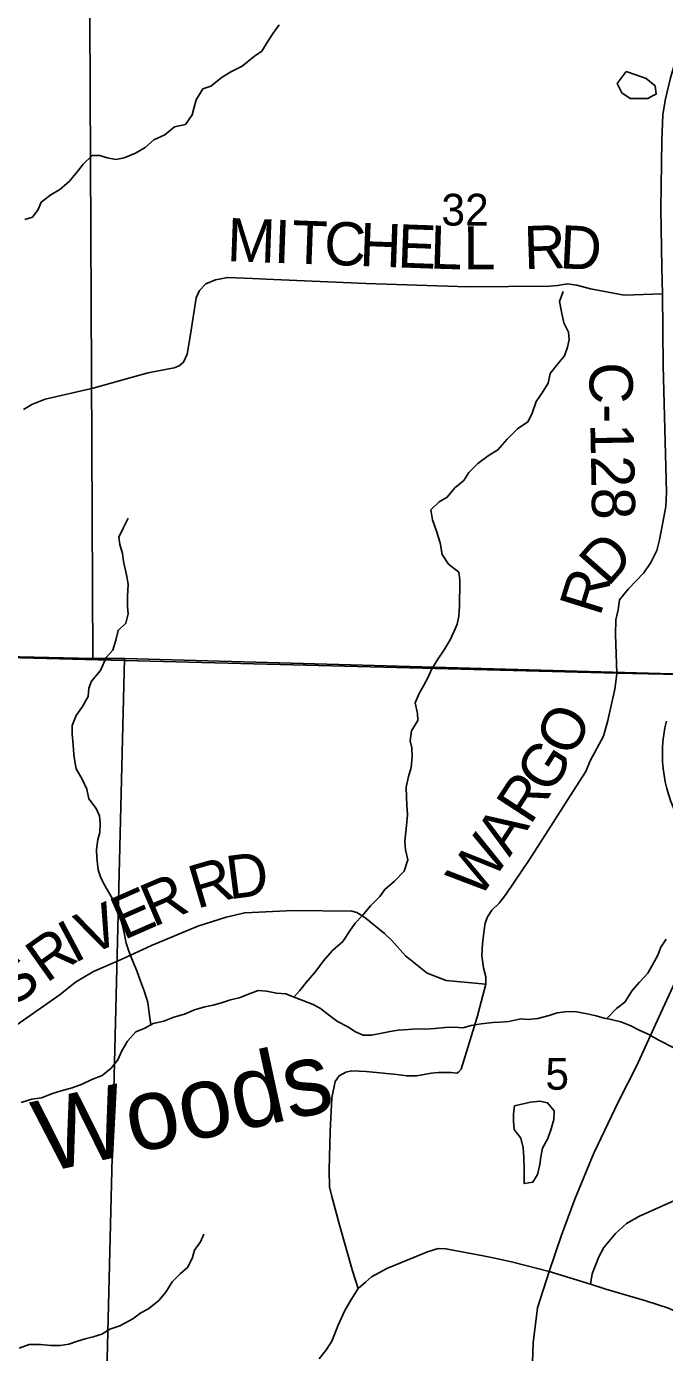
# Model space of a CAD drawing. Extents: x 2043100 to 2470832, y 443715 to 810583.
# Drawn here: x 2231654 to 2236081, y 666237 to 675442 of the extents above; entities that cross this region are included whole.
import ezdxf

# ---------------------------------------------------------------- set-up
doc = ezdxf.new("R2010")
doc.units = 0
for name, color, linetype in [('GM_X_County_Road', 7, 'Continuous'), ('GM_X_County_Road_Text', 7, 'Continuous'), ('GM_X_Interstate_Route', 7, 'Continuous'), ('GM_X_Interstate_Shield', 7, 'Continuous'), ('GM_X_Minor_Lake', 7, 'Continuous'), ('GM_X_Minor_River', 7, 'Continuous'), ('GM_X_Minor_River_Text', 7, 'Continuous'), ('GM_X_Section', 7, 'Continuous'), ('GM_X_Section_Text', 7, 'Continuous'), ('GM_X_Township', 7, 'Continuous'), ('GM_X_Township_Road', 7, 'Continuous'), ('GM_X_Township_Road_Text', 7, 'Continuous')]:
    doc.layers.add(name, color=color, linetype=linetype)

msp = doc.modelspace()

# ---------------------------------------------------------------- linework, layer by layer
at = {"layer": 'GM_X_County_Road'}
for points in [[(2235748.3, 670928.3), (2235751.5, 670952.9), (2235742.4, 671220.3), (2235743.7, 671322.2), (2235761, 671391.1), (2235768.7, 671460.5), (2235830.1, 671535), (2235937.3, 671650.1), (2235986.8, 671720.5), (2236028.1, 671805), (2236047.6, 671879.2), (2236076.5, 672035.7), (2236090, 672109.9), (2236095.3, 672208.1), (2236073.1, 673087.1), (2236067.6, 673585.7), (2236062.3, 673767.9), (2236057.4, 674176.4), (2236064.1, 674647.1), (2236070.8, 674831.3), (2236088, 674939.6), (2236123, 675086.1), (2236214.8, 675397.2), (2236277.2, 675620)], [(2234788.4, 668589.8), (2234788.9, 668591.7), (2234842, 668793.3), (2234841.6, 668843.4), (2234825.2, 668907.3), (2234814.6, 668993.4), (2234818, 669073.5), (2234831.3, 669169.8), (2234837, 669217.9), (2234852.7, 669262.1), (2234884.3, 669308.4), (2234933.9, 669356.9), (2234979.5, 669415.3), (2235143.7, 669659), (2235309.8, 669916.7), (2235426.4, 670101.8), (2235535.2, 670270.9), (2235566.7, 670343.3), (2235659, 670515.6), (2235689.4, 670624.2), (2235737.1, 670841.5), (2235748.3, 670928.3)], [(2231470.1, 668430.1), (2231887.9, 668721.8), (2231993.2, 668806.7), (2232118.6, 668881.9), (2232312, 668965.5), (2232521.2, 669061.3), (2232842.1, 669196), (2233039.5, 669257.7), (2233169.3, 669288.8), (2233507, 669305.5), (2233910.8, 669300.7), (2233946.9, 669290.9), (2234003.1, 669255.3), (2234137.8, 669146.2), (2234190.1, 669096.6), (2234284.8, 668989.2), (2234435.6, 668870.2), (2234565.9, 668819.1), (2234842, 668793.3)], [(2233955.8, 666681), (2233916.5, 666802.9), (2233828.4, 667114.7), (2233772.9, 667318.6), (2233756.5, 667386.5), (2233753.6, 667504.7), (2233761.7, 667773.2), (2233774.1, 668003.6), (2233797.3, 668118), (2233823, 668158.3), (2233870.8, 668182.7), (2233910.7, 668191), (2234010.7, 668187.8), (2234224.7, 668165.5), (2234292.7, 668158), (2234362.7, 668156.5), (2234462.5, 668175.4), (2234512.5, 668179.8), (2234600.4, 668180.5), (2234640.4, 668176.8), (2234652.4, 668182.9), (2234670.2, 668203.1), (2234779.7, 668556.5), (2234788.4, 668589.8)], [(2235567.1, 666711.6), (2235579.1, 666782.6), (2235625.1, 666901.6), (2235659.9, 666966.3), (2235742.3, 667062), (2235819, 667131.5), (2235908.1, 667183.2), (2236372.4, 667392), (2236554.8, 667485.4), (2236679.5, 667559.8), (2236912.6, 667722.3), (2237104.2, 667858.1), (2237185.2, 667915.6), (2237420.4, 668074.1), (2237513.4, 668129.8), (2237628.5, 668184), (2237767.8, 668224.3), (2237779.4, 668227.6)], [(2233686.3, 666191.8), (2233736.2, 666258), (2233774.1, 666314.2), (2233818, 666426.4), (2233859.9, 666524.6), (2233905.8, 666600.8), (2233955.8, 666681), (2234007.7, 666725.1), (2234047.6, 666761.2), (2234155.6, 666819.5), (2234437.4, 666936.1), (2234511.3, 666958.3), (2234565.3, 666956.3), (2234823.2, 666908.7), (2234880.8, 666896), (2234881.2, 666895.9)], [(2234881.2, 666895.9), (2234967.2, 666876.9), (2235029.2, 666862.9), (2235282.4, 666798.9), (2235567.1, 666711.6), (2235675.1, 666675.7), (2235951.1, 666596), (2236109.1, 666544.2), (2236175.1, 666514.2), (2236246.3, 666465.7), (2236246.7, 666465.5)]]:
    msp.add_lwpolyline(points, dxfattribs=at)
at = {"layer": 'GM_X_Interstate_Route'}
msp.add_lwpolyline([(2235161.2, 666032.3), (2235170.2, 666303), (2235201.3, 666545.9), (2235282.4, 666798.9), (2235365.8, 667051.9), (2235459.2, 667301.3), (2235591.9, 667619.2), (2235762.2, 667979.6), (2235887.7, 668223.4), (2236055.9, 668593.7), (2236241.8, 668994.3), (2236404.6, 669310.5), (2236537.9, 669576.3), (2236662.8, 669876.1), (2236767.3, 670193.5), (2236871.9, 670530.8), (2236935, 670928.2), (2236962.4, 671258.1), (2236970.9, 671749.7), (2236947, 672108.3), (2236889.3, 672310), (2236776, 673758.8), (2236599.3, 675527.4)], dxfattribs=at)
at = {"layer": 'GM_X_Interstate_Shield'}
msp.add_arc((2237004.3, 670389.5), 937.5, 165.80665, 258.46304, dxfattribs=at)
at = {"layer": 'GM_X_Minor_Lake'}
for points in [[(2235816.7, 675130.5), (2235753, 675046.2), (2235785.2, 674980.3), (2235843.3, 674942.5), (2235965.2, 674942.9), (2236008.5, 674965.5)], [(2236008.5, 674965.5), (2236023.1, 674973.1), (2236017, 675029.1), (2235954.8, 675081), (2235882.8, 675106.7), (2235816.7, 675130.5)], [(2235040.6, 667949.6), (2235034.7, 667893.5), (2235034.9, 667843.4), (2235039.1, 667785.4), (2235085.2, 667723.5), (2235101.4, 667657.5), (2235105.6, 667589.4), (2235107.9, 667509.3), (2235108.2, 667409.2), (2235168.1, 667419.5), (2235193.2, 667460.6)], [(2235193.2, 667460.6), (2235199.9, 667471.6), (2235215.7, 667541.8), (2235223.6, 667593.8), (2235235.4, 667654), (2235271.1, 667722.2), (2235294.9, 667790.3), (2235314.7, 667854.4), (2235316.6, 667914.5), (2235270.4, 667970.4), (2235216.4, 667982.2), (2235152.4, 667974), (2235040.6, 667949.6)]]:
    msp.add_lwpolyline(points, dxfattribs=at)
at = {"layer": 'GM_X_Minor_River'}
for points in [[(2231641.6, 674102.9), (2231695.5, 674119.1), (2231735.4, 674171.3), (2231755.2, 674221.4), (2231823, 674273.7), (2231884.9, 674309.9), (2231950.7, 674366.2), (2232008.5, 674434.4), (2232046.3, 674486.6), (2232110.1, 674546.9), (2232162.1, 674545.1), (2232214.1, 674529.2), (2232274.1, 674519.4), (2232332, 674529.7), (2232409.9, 674562), (2232477.8, 674602.2), (2232537.6, 674654.5), (2232613.5, 674688.8), (2232681.3, 674745.1), (2232757.2, 674761.4), (2232803, 674827.6), (2232818.8, 674881.7), (2232832.6, 674931.8), (2232878.4, 675008), (2232934.3, 675028.2), (2233012.1, 675090.5), (2233072, 675126.8), (2233151.8, 675167.1), (2233235.6, 675235.4), (2233287.4, 675271.7), (2233331.2, 675341.9), (2233365, 675396), (2233406.8, 675452.2)], [(2233509.5, 668703.1), (2233550.8, 668749.1), (2233604.6, 668817.3), (2233654.4, 668875.5), (2233714.1, 668955.8), (2233777.9, 669028.1), (2233849.6, 669090.4), (2233897.4, 669164.7), (2233935.2, 669216.9), (2233985, 669271.1), (2234040.8, 669337.4), (2234106.6, 669401.7), (2234140.4, 669451.8), (2234208.2, 669508.1), (2234274, 669578.4), (2234299.7, 669656.6), (2234283.5, 669726.6), (2234279.4, 669786.6), (2234291, 669894.8), (2234298.8, 669968.9), (2234292.6, 670036.9), (2234290.4, 670090.9), (2234288.2, 670161), (2234306, 670235.1), (2234323.8, 670297.2), (2234331.6, 670371.3), (2234329.4, 670433.4), (2234317.2, 670483.4), (2234325, 670551.5), (2234368.8, 670623.7), (2234368.7, 670673.7), (2234352.4, 670745.8), (2234378.2, 670811.9), (2234408.1, 670864), (2234441.9, 670924.2), (2234465.7, 670978.3), (2234509.5, 671048.6), (2234553.2, 671114.8), (2234595, 671185), (2234622.8, 671243.1), (2234642.7, 671293.2), (2234654.5, 671349.3), (2234658.3, 671417.4), (2234660.1, 671471.5), (2234662, 671533.5), (2234661.8, 671601.6), (2234653.6, 671653.6), (2234583.5, 671709.4), (2234539.3, 671777.3), (2234525, 671857.3), (2234498.8, 671939.3), (2234472.6, 672017.3), (2234460.4, 672085.3), (2234518.2, 672141.5), (2234574.1, 672173.8), (2234625.9, 672238), (2234689.7, 672290.3), (2234723.5, 672346.4), (2234787.3, 672408.7), (2234857.1, 672461), (2234924.9, 672503.3), (2234988.7, 672577.6), (2235062.5, 672647.9), (2235132.3, 672696.2), (2235160.1, 672750.3), (2235191.8, 672838.5), (2235233.6, 672898.7), (2235273.4, 672966.9), (2235287.2, 673033), (2235341, 673099.2), (2235388.8, 673155.4), (2235408.6, 673215.6), (2235420.4, 673269.7), (2235416.3, 673319.7), (2235384.1, 673385.6), (2235365.9, 673461.6), (2235353.7, 673533.6), (2235379.5, 673601.8)], [(2232518.1, 668512.4), (2232505.7, 668593.2), (2232495.5, 668667.2), (2232473.3, 668741.2), (2232445.1, 668815.2), (2232420.9, 668887.2), (2232388.7, 668957.2), (2232364.5, 669023.1), (2232346.3, 669077.1), (2232332.1, 669149.1), (2232317.9, 669209.1), (2232301.8, 669267.1), (2232277.6, 669333.1), (2232241.4, 669403), (2232199.2, 669475), (2232171, 669530.9), (2232150.9, 669586.9), (2232142.6, 669670.9), (2232140.5, 669729), (2232150.2, 669797.1), (2232162.1, 669847.2), (2232165.9, 669911.2), (2232161.7, 669961.3), (2232137.6, 670013.2), (2232087.4, 670079.1), (2232073.2, 670147.1), (2232041, 670217.1), (2231998.8, 670289), (2231988.7, 670339), (2231982.5, 670389), (2231978.3, 670455.1), (2231972.1, 670529.1), (2231969.9, 670589.2), (2231999.7, 670659.3), (2232043.5, 670721.5), (2232081.3, 670791.7), (2232087.1, 670847.8), (2232105, 670897.9), (2232166.7, 670972.2), (2232206.4, 671062.4), (2232252.3, 671112.6), (2232274, 671182.7), (2232289.8, 671248.8), (2232343.7, 671299.1), (2232359.5, 671365.2), (2232355.3, 671415.2), (2232355.1, 671485.3), (2232360.8, 671569.4), (2232348.7, 671635.4), (2232328.4, 671727.4), (2232320.2, 671783.4), (2232302, 671845.4), (2232295.9, 671897.4), (2232327.7, 671963.6), (2232359.5, 672027.8)], [(2235682.1, 668554.5), (2235748.2, 668624.8), (2235806.1, 668669), (2235857.8, 668749.3), (2235907.6, 668807.5), (2235965.4, 668869.8), (2235999.2, 668927.9), (2236035, 668994.1), (2236056.8, 669050.2), (2236092.6, 669106.4)], [(2231618, 667971.5), (2231691.8, 667995.8), (2231757.8, 668004), (2231835.7, 668034.3), (2231895.6, 668052.5), (2231971.5, 668072.8), (2232039.4, 668099.1), (2232107.3, 668131.4), (2232179.1, 668159.6), (2232241, 668209.9), (2232288.8, 668268.1), (2232316.6, 668330.3), (2232354.4, 668398.5), (2232412.1, 668462.8), (2232476, 668489), (2232533.9, 668521.2), (2232607.8, 668537.5), (2232677.7, 668563.8), (2232751.6, 668586.1), (2232819.5, 668616.3), (2232891.4, 668636.6), (2232949.4, 668646.8), (2233007.3, 668665.1), (2233069.2, 668685.3), (2233131.1, 668699.5), (2233207, 668727.8), (2233262.9, 668750), (2233318.9, 668744.2), (2233388.9, 668730.5), (2233452.9, 668726.7), (2233504.9, 668704.9), (2233571, 668679.1), (2233643, 668653.3), (2233695.1, 668625.5), (2233747.2, 668583.6), (2233813.3, 668533.8), (2233883.4, 668498), (2233937.5, 668462.2), (2233991.5, 668440.3), (2234047.5, 668440.5), (2234119.4, 668452.8), (2234177.4, 668465), (2234233.3, 668473.2), (2234305.3, 668479.5), (2234361.2, 668483.7)], [(2234361.2, 668483.7), (2234423.2, 668481.9), (2234487.2, 668486.1), (2234559.1, 668492.4), (2234621.1, 668494.6), (2234683.1, 668490.8), (2234739, 668507), (2234808.9, 668517.3), (2234890.9, 668527.6), (2234942.8, 668529.8), (2235000.8, 668534), (2235084.7, 668552.3), (2235136.7, 668548.5), (2235202.7, 668554.7), (2235280.6, 668577), (2235336.5, 668595.3), (2235390.4, 668601.4), (2235460.4, 668603.7), (2235544.4, 668588), (2235608.4, 668574.2), (2235662.5, 668558.4), (2235712.5, 668548.5), (2235778.5, 668532.8), (2235848.5, 668505), (2235900.6, 668477.1), (2235968.7, 668447.4), (2236042.8, 668405.6), (2236142.9, 668353.9)], [(2231603.1, 666267.7), (2231673, 666291.9), (2231751, 666292.2), (2231823, 666284.4), (2231886.9, 666284.7), (2231948.9, 666294.9), (2232008.8, 666315.1), (2232060.7, 666331.3), (2232116.7, 666345.5), (2232176.6, 666363.8), (2232232.5, 666398), (2232302.4, 666422.3), (2232392.2, 666470.7), (2232448, 666510.9), (2232501.9, 666539.1), (2232571.7, 666597.4), (2232621.5, 666655.7), (2232665.3, 666727.9), (2232721.1, 666782.2), (2232772.9, 666828.4), (2232806.7, 666896.6), (2232820.5, 666946.7), (2232862.4, 667004.9), (2232884.2, 667057)]]:
    msp.add_lwpolyline(points, dxfattribs=at)
at = {"layer": 'GM_X_Section'}
for points in [[(2237342.8, 676305.5), (2237290.7, 670914.8), (2232335.3, 671053.3), (2232115.2, 671055.1), (2232088.9, 676483)], [(2226729.8, 671177.1), (2232115.2, 671055.1), (2232335.3, 671053.3), (2232196.6, 665535.6), (2226609.8, 665587.6), (2226612.4, 665913.8)], [(2232335.3, 671053.3), (2237290.7, 670914.8), (2237638.9, 670912.4), (2237531.1, 665493.1), (2232196.6, 665535.6)]]:
    msp.add_lwpolyline(points, close=True, dxfattribs=at)
at = {"layer": 'GM_X_Township'}
for points in [[(2258825.8, 676651), (2258742.3, 671669), (2258672.2, 670481.8), (2256458.7, 670526.3), (2250661.2, 670642.8), (2248089.5, 670694.5), (2247937.9, 670697.9), (2247527.7, 670707.3), (2242813.7, 670786.8), (2238408.3, 670897.5), (2236935, 670928.2), (2235751.5, 670952.9), (2228190.1, 671146.6)], [(2228190.1, 671146.6), (2235751.5, 670952.9), (2236935, 670928.2), (2238408.3, 670897.5), (2242813.7, 670786.8), (2247527.7, 670707.3), (2247937.9, 670697.9), (2248089.5, 670694.5), (2248085.7, 670382.7), (2248027.9, 667139.4), (2247905.3, 659948.7)]]:
    msp.add_lwpolyline(points, dxfattribs=at)
at = {"layer": 'GM_X_Township_Road'}
msp.add_lwpolyline([(2231633.3, 672783.5), (2231691.1, 672818), (2231782.8, 672854.7), (2232116.1, 672931.5), (2232381.4, 673005.7), (2232499.1, 673036.7), (2232678.8, 673072.1), (2232714.7, 673086.4), (2232744.5, 673110.7), (2232770.1, 673167), (2232791.1, 673303.3), (2232831.3, 673558), (2232854.9, 673610.2), (2232898.6, 673654.7), (2232966.4, 673683.2), (2233050.2, 673699.9), (2233222.2, 673693.3), (2233318.2, 673688), (2234012.1, 673657.5), (2234717.9, 673635.1), (2235281.6, 673639.5), (2235339.5, 673644), (2235407.4, 673654.6), (2235473.4, 673645.1), (2235567.6, 673619.8), (2235801.8, 673577.6), (2236067.6, 673585.7)], dxfattribs=at)

# ---------------------------------------------------------------- texts
at = {"layer": 'GM_X_County_Road_Text'}
for s, rotation, p in [('C-128', 271.10616, (2235558.7, 673108.2)), ('D', 48.65233, (2235691, 671546.5)), ('R', 72.68951, (2235633.9, 671340)), ('O', 64.74464, (2235448.2, 670360.9)), ('G', 57.6471, (2235287.4, 670102.3)), ('R', 56.86307, (2235150.3, 669892.2)), ('A', 56.91668, (2235006.2, 669671.1)), ('W', 54.02876, (2234792.7, 669376.2)), ('R', 16.44989, (2232836.5, 669315)), ('D', 7.37126, (2233060.6, 669382.2)), ('R', 23.25035, (2232533, 669187.1)), ('E', 23.69661, (2232328.1, 669097.2)), ('V', 24.17775, (2232087.8, 668989.4)), ('I', 27.96504, (2231983.7, 668933.9)), ('R', 35.37252, (2231791.5, 668796.6)), ('S', 35.15434, (2231549.3, 668625.3))]:
    msp.add_text(s, height=300, rotation=rotation, dxfattribs=at).set_placement(p)
at = {"layer": 'GM_X_Minor_River_Text'}
msp.add_text('Woods', height=499.98, rotation=12.21199, dxfattribs=at).set_placement((2231773.8, 667483.1))
at = {"layer": 'GM_X_Section_Text'}
for s, height, p in [('32', 220.83, (2234533.2, 674059.6)), ('5', 220.8, (2235254.8, 668060.8))]:
    msp.add_text(s, height=height, rotation=0.00001, dxfattribs=at).set_placement(p)
at = {"layer": 'GM_X_Township_Road_Text'}
for s, rotation, p in [('M', 357.89956, (2233042.6, 673813.3)), ('I', 357.8964, (2233368, 673801.4)), ('T', 357.89869, (2233491.1, 673796.9)), ('C', 357.89971, (2233715.4, 673788.7)), ('H', 357.89765, (2233961.6, 673779.6)), ('E', 357.90679, (2234225.5, 673770)), ('L', 358.33097, (2234452.2, 673761.7)), ('L', 0.22639, (2234687.3, 673755)), ('R', 1.83868, (2235110, 673756)), ('D', 357.18307, (2235349.8, 673764))]:
    msp.add_text(s, height=300, rotation=rotation, dxfattribs=at).set_placement(p)

doc.saveas('drawing.dxf')
